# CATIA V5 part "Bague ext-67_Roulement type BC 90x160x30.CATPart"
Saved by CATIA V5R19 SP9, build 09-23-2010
Part number: Bague ext-67_Roulement type BC 90x160x30
Revision: ANY
Definition: UNKNOWN
Nomenclature: Bague ext-67_Roulement type BC 90x160x30
Source: Unknown
Bounding box of the stored display mesh (mm): x -15 to 15, y -79.813 to 79.813, z -80 to 80
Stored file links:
  Y:\fin de projet cabestan poupee\Bague ext-67_Roulement type BC 90x160x30.CATPart
  Ass_arbre poupee_1.CATProduct
  Y:\bricolage cabestan\6_axe.CATPart
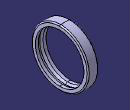
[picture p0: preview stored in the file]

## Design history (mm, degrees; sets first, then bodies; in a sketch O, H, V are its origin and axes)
Body1 "NONE" (main body)
  Solid1: solid without history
